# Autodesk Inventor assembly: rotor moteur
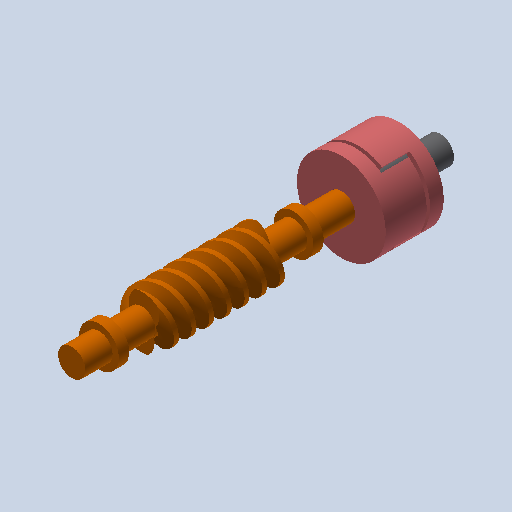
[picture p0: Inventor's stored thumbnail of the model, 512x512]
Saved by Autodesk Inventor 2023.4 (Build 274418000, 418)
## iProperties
Created: 2011-01
Part Number: rotor moteur
Document SubType Name: Assembly
Designer: eric
Mass: 15.8906 g
Surface Area: 104.881 cm^2
Volume: 15.8906 cm^3
Density: 1 g/cm^3
Author: eric
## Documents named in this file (5)
- C:\Users\bruno\Documents\1-Cours-2024-25\TSsI\7-Dynamique\chariot de golf\chariot_de_golf\chariot_de_golf_trolem\rotor moteur.iam
- C:\Users\bruno\Documents\1-Cours-2024-25\TSsI\7-Dynamique\chariot de golf\chariot_de_golf\chariot_de_golf_trolem\12Vis-sans-fin_Defaut.ipt
- C:\Users\bruno\Documents\1-Cours-2024-25\TSsI\7-Dynamique\chariot de golf\chariot_de_golf\chariot_de_golf_trolem\12manchon_accouplement_Defaut.ipt
- C:\Users\bruno\Documents\1-Cours-2024-25\TSsI\7-Dynamique\chariot de golf\chariot_de_golf\chariot_de_golf_trolem\12croix_elastique_Defaut.ipt
- C:\Users\bruno\Documents\1-Cours-2024-25\TSsI\7-Dynamique\chariot de golf\chariot_de_golf\chariot_de_golf_trolem\12axe_moteur_Defaut.ipt
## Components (5 placed, 4 different names)
1. 12Vis-sans-fin_Defaut:1
2. 12croix_elastique_Defaut:1
3. 12manchon_accouplement_Defaut:2
4. 12axe_moteur_Defaut:1
5. 12manchon_accouplement_Defaut:1
